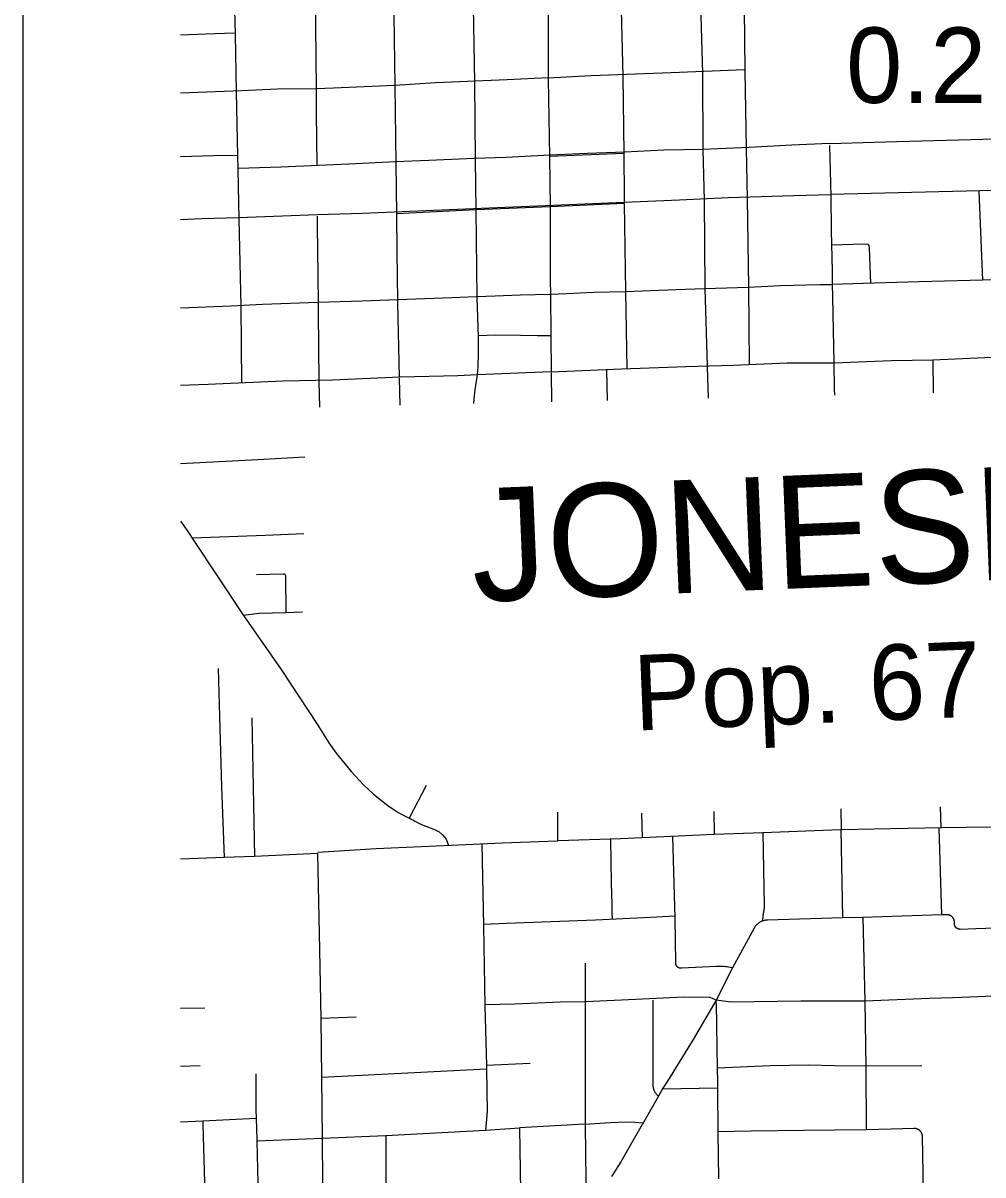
# Model space of a CAD drawing. Extents: x 309348 to 309445, y 336383 to 336484.
# Drawn here: x 309347.661 to 309348.736, y 336398.714 to 336400.005 of the extents above; entities that cross this region are included whole.
import ezdxf

# ---------------------------------------------------------------- set-up
doc = ezdxf.new("R2010")
doc.units = 0
doc.layers.add('R_Annotation', color=7, linetype='Continuous')
doc.layers.add('R_Border Notes', color=7, linetype='Continuous')

msp = doc.modelspace()

# ---------------------------------------------------------------- linework, layer by layer
at = {"layer": 'R_Annotation'}
msp.add_line((309348.736, 336399.7168), (309348.7321, 336399.8167), dxfattribs=at)
for points in [[(309348.4191, 336400.053), (309348.4191, 336400.0524), (309348.4222, 336399.9485)], [(309348.0759, 336400.0402), (309348.0772, 336399.9351)], [(309348.1648, 336400.0446), (309348.1667, 336399.9388)], [(309348.2491, 336400.0465), (309348.2492, 336399.9422)], [(309348.3301, 336400.0497), (309348.3327, 336399.9455)], [(309347.8972, 336400.0337), (309347.8982, 336399.9928)], [(309347.9881, 336400.0366), (309347.9893, 336399.9315)], [(309348.4687, 336400.0211), (309348.4696, 336399.9515)], [(309347.8371, 336399.992), (309347.8653, 336399.993), (309347.8972, 336399.9943)], [(309347.8982, 336399.9928), (309347.8996, 336399.9275)], [(309348.2492, 336399.9437), (309348.2972, 336399.9462), (309348.3869, 336399.9498), (309348.4696, 336399.9529)], [(309348.4696, 336399.9515), (309348.4711, 336399.8646)], [(309348.2492, 336399.9437), (309348.2033, 336399.9415), (309348.123, 336399.9382), (309348.0772, 336399.9351)], [(309348.1667, 336399.9388), (309348.1674, 336399.8519)], [(309348.2492, 336399.9422), (309348.2506, 336399.8556)], [(309348.3327, 336399.9455), (309348.3337, 336399.859)], [(309348.4222, 336399.9485), (309348.4224, 336399.8629)], [(309347.9893, 336399.9315), (309347.9454, 336399.931), (309347.9055, 336399.9292), (309347.8468, 336399.9269), (309347.8371, 336399.9265)], [(309347.8996, 336399.9275), (309347.901, 336399.8567)], [(309347.9893, 336399.9315), (309347.9891, 336399.9045), (309347.9899, 336399.8454)], [(309348.0772, 336399.9351), (309348.0086, 336399.9323), (309347.9893, 336399.9315)], [(309348.0772, 336399.9351), (309348.0783, 336399.8477)], [(309348.5645, 336399.87), (309348.6399, 336399.8725), (309348.7228, 336399.8746), (309348.7904, 336399.8766), (309348.8422, 336399.8777), (309348.8945, 336399.8787), (309348.9447, 336399.8795), (309348.9871, 336399.881), (309349.0202, 336399.8814)], [(309348.5645, 336399.87), (309348.5222, 336399.8682), (309348.4743, 336399.8658), (309348.4229, 336399.8635), (309348.3786, 336399.8625), (309348.3351, 336399.8602), (309348.2929, 336399.8589), (309348.2514, 336399.8571), (309348.2017, 336399.8545), (309348.1662, 336399.8532), (309348.1153, 336399.8512), (309348.0782, 336399.8494), (309348.0257, 336399.8471), (309347.9495, 336399.8435), (309347.9016, 336399.8422)], [(309348.3337, 336399.859), (309348.2506, 336399.8556)], [(309348.3337, 336399.859), (309348.3337, 336399.8578), (309348.3343, 336399.8114), (309348.3344, 336399.8028)], [(309348.4224, 336399.8629), (309348.4238, 336399.8065)], [(309348.4711, 336399.8646), (309348.4721, 336399.8085)], [(309348.5645, 336399.8679), (309348.5657, 336399.8111)], [(309347.901, 336399.8567), (309347.8738, 336399.8563), (309347.8371, 336399.8551)], [(309347.901, 336399.8567), (309347.9013, 336399.8409)], [(309348.0783, 336399.8477), (309348.079, 336399.7914)], [(309348.1674, 336399.8519), (309348.168, 336399.7958)], [(309348.2506, 336399.8556), (309348.2512, 336399.7991)], [(309347.9013, 336399.8409), (309347.9025, 336399.7854)], [(309347.9024, 336399.7871), (309347.9901, 336399.7904), (309348.0409, 336399.7922), (309348.1294, 336399.7958), (309348.2993, 336399.8028), (309348.3961, 336399.8071), (309348.4507, 336399.8095), (309348.5245, 336399.8118), (309348.5656, 336399.8128)], [(309348.4721, 336399.8085), (309348.4734, 336399.709)], [(309348.7934, 336399.8187), (309348.5656, 336399.8128)], [(309348.5657, 336399.8111), (309348.5663, 336399.7725), (309348.5673, 336399.7269), (309348.5675, 336399.7119)], [(309348.168, 336399.7958), (309348.079, 336399.7914)], [(309348.2512, 336399.7991), (309348.168, 336399.7958)], [(309348.168, 336399.7958), (309348.169, 336399.6973)], [(309348.3344, 336399.8028), (309348.2512, 336399.7991)], [(309348.2512, 336399.7991), (309348.2512, 336399.7562), (309348.2513, 336399.7182), (309348.2516, 336399.7001)], [(309348.3344, 336399.8028), (309348.3356, 336399.7043)], [(309348.4238, 336399.8065), (309348.4248, 336399.7076)], [(309347.8371, 336399.7849), (309347.8612, 336399.786), (309347.9024, 336399.7871)], [(309347.9025, 336399.7854), (309347.9047, 336399.6876)], [(309347.9901, 336399.7885), (309347.9904, 336399.7781), (309347.991, 336399.7224), (309347.9912, 336399.6905)], [(309348.079, 336399.7914), (309348.0794, 336399.7491), (309348.0803, 336399.6939)], [(309348.5666, 336399.7566), (309348.603, 336399.7575), (309348.6074, 336399.7571), (309348.6083, 336399.7559), (309348.6089, 336399.7531), (309348.6091, 336399.7429), (309348.6102, 336399.7133)], [(309348.7942, 336399.7185), (309348.736, 336399.7168)], [(309348.1689, 336399.6985), (309348.1897, 336399.6994), (309348.2179, 336399.7003), (309348.2516, 336399.7013), (309348.2698, 336399.7018), (309348.3004, 336399.7033), (309348.3356, 336399.7043)], [(309348.3356, 336399.7043), (309348.3924, 336399.7065), (309348.4243, 336399.7075), (309348.4734, 336399.709)], [(309348.3356, 336399.7043), (309348.3371, 336399.6179)], [(309348.4248, 336399.7076), (309348.4274, 336399.6208)], [(309348.4734, 336399.709), (309348.5095, 336399.7108), (309348.5533, 336399.7121), (309348.5675, 336399.7119)], [(309348.4734, 336399.709), (309348.4743, 336399.6225)], [(309348.665, 336399.7149), (309348.6019, 336399.7131), (309348.5675, 336399.7119)], [(309348.5675, 336399.7119), (309348.5677, 336399.6984), (309348.5685, 336399.6605), (309348.5691, 336399.6243)], [(309348.736, 336399.7168), (309348.665, 336399.7149)], [(309347.8371, 336399.6858), (309347.894, 336399.6883), (309347.9291, 336399.69), (309347.9911, 336399.6921)], [(309347.9911, 336399.6921), (309348.0406, 336399.6939), (309348.0707, 336399.6947), (309348.1412, 336399.6974), (309348.1689, 336399.6985)], [(309348.0803, 336399.6939), (309348.0804, 336399.692), (309348.0821, 336399.6081)], [(309348.169, 336399.6973), (309348.1707, 336399.6535)], [(309348.2516, 336399.7001), (309348.2522, 336399.6553)], [(309347.9047, 336399.6876), (309347.9053, 336399.6016)], [(309347.9912, 336399.6905), (309347.9912, 336399.6893), (309347.9915, 336399.6807), (309347.992, 336399.6034)], [(309348.1707, 336399.6535), (309348.1708, 336399.6446), (309348.1708, 336399.6347), (309348.1703, 336399.6199), (309348.1697, 336399.6108)], [(309348.1707, 336399.6548), (309348.1905, 336399.6555), (309348.2181, 336399.6553), (309348.2366, 336399.6549), (309348.2522, 336399.6549)], [(309348.2522, 336399.6553), (309348.2525, 336399.6142)], [(309348.5691, 336399.6243), (309348.6338, 336399.627), (309348.6801, 336399.6275), (309348.7383, 336399.6301), (309348.793, 336399.6313)], [(309348.6801, 336399.6275), (309348.6806, 336399.5905)], [(309348.2525, 336399.6142), (309348.1697, 336399.6108)], [(309348.2525, 336399.6142), (309348.3316, 336399.6177), (309348.4034, 336399.62), (309348.4564, 336399.6218), (309348.517, 336399.6241), (309348.5691, 336399.6243)], [(309348.3143, 336399.6169), (309348.3151, 336399.5821)], [(309348.4274, 336399.6196), (309348.4274, 336399.6193), (309348.4283, 336399.5847)], [(309348.5691, 336399.6243), (309348.5696, 336399.5951), (309348.5698, 336399.5879)], [(309348.1697, 336399.6108), (309348.1479, 336399.6098), (309348.0834, 336399.6082), (309348.0073, 336399.605), (309347.9519, 336399.6038), (309347.868, 336399.5999), (309347.8371, 336399.5989)], [(309347.992, 336399.6034), (309347.9927, 336399.5747)], [(309348.0822, 336399.6069), (309348.083, 336399.5768)], [(309348.1696, 336399.6101), (309348.168, 336399.6015), (309348.1668, 336399.5941), (309348.1657, 336399.5844), (309348.1654, 336399.5787)], [(309348.2526, 336399.613), (309348.253, 336399.5807)], [(309347.9766, 336399.5184), (309347.9239, 336399.5154), (309347.8371, 336399.5111)], [(309347.8371, 336399.4469), (309347.8453, 336399.4352), (309347.851, 336399.4267)], [(309347.8501, 336399.4281), (309347.9321, 336399.4311), (309347.9753, 336399.4329)], [(309347.851, 336399.4267), (309347.9077, 336399.3411)], [(309347.9222, 336399.3872), (309347.9522, 336399.3876), (309347.9525, 336399.3877), (309347.9528, 336399.3877), (309347.9531, 336399.3877), (309347.9534, 336399.3876), (309347.9537, 336399.3875), (309347.954, 336399.3873), (309347.9542, 336399.3871), (309347.9544, 336399.3868), (309347.9545, 336399.3865), (309347.9546, 336399.3862), (309347.9547, 336399.3859), (309347.9547, 336399.3859), (309347.9553, 336399.3446)], [(309347.9074, 336399.3416), (309347.9254, 336399.3438), (309347.9553, 336399.3446), (309347.974, 336399.3452)], [(309347.9077, 336399.3411), (309347.9498, 336399.2804), (309347.9903, 336399.2191), (309348.0033, 336399.1985), (309348.0116, 336399.1868), (309348.0283, 336399.1662), (309348.0422, 336399.1513), (309348.0532, 336399.1408), (309348.0695, 336399.128), (309348.0809, 336399.1202), (309348.0903, 336399.1154), (309348.1072, 336399.1067), (309348.1219, 336399.1012), (309348.1269, 336399.0987), (309348.1306, 336399.0953), (309348.1347, 336399.0905), (309348.1375, 336399.0831)], [(309347.8794, 336399.2818), (309347.8809, 336399.2278)], [(309347.8809, 336399.2278), (309347.883, 336399.1491)], [(309347.917, 336399.2264), (309347.9202, 336399.0711)], [(309347.883, 336399.1491), (309347.8861, 336399.07)], [(309348.1124, 336399.1505), (309348.0933, 336399.1139)], [(309348.5769, 336399.1242), (309348.5773, 336399.101)], [(309348.6884, 336399.1266), (309348.6891, 336399.1029)], [(309348.2594, 336399.1208), (309348.2596, 336399.0883)], [(309348.3535, 336399.1194), (309348.3543, 336399.0919)], [(309348.4346, 336399.1212), (309348.4351, 336399.0956)], [(309348.4898, 336399.0973), (309348.4351, 336399.0956)], [(309348.4898, 336399.0973), (309348.4911, 336399.0159), (309348.4911, 336399.0148), (309348.4911, 336399.0137), (309348.491, 336399.0126), (309348.4909, 336399.0115), (309348.4907, 336399.0104), (309348.4905, 336399.0093), (309348.4903, 336399.0082), (309348.4901, 336399.0071), (309348.4899, 336399.0059), (309348.4897, 336399.0047), (309348.4896, 336399.0035), (309348.4895, 336399.0023), (309348.4894, 336399.0011), (309348.4894, 336398.9999), (309348.4894, 336398.9987)], [(309348.5771, 336399.101), (309348.5768, 336399.101), (309348.4898, 336399.0973)], [(309348.6898, 336399.1029), (309348.5768, 336399.101)], [(309348.5771, 336399.101), (309348.5788, 336399.0022)], [(309348.687, 336399.1028), (309348.69, 336399.0055)], [(309348.8015, 336399.1046), (309348.6898, 336399.1029)], [(309348.2596, 336399.0883), (309348.1976, 336399.0857), (309348.1404, 336399.0832), (309348.0562, 336399.0795), (309347.991, 336399.0756)], [(309348.1748, 336399.0847), (309348.1767, 336398.9934)], [(309348.4351, 336399.0956), (309348.3301, 336399.0909), (309348.2604, 336399.0884)], [(309348.319, 336399.0905), (309348.3196, 336399.0411), (309348.3203, 336399.0175), (309348.3205, 336399.0098), (309348.3208, 336399.0005)], [(309348.3883, 336399.0935), (309348.3909, 336399.002)], [(309347.9906, 336399.0744), (309347.9202, 336399.0711)], [(309347.9906, 336399.0744), (309347.9928, 336398.9664)], [(309347.8861, 336399.07), (309347.8371, 336399.0679)], [(309347.9202, 336399.0711), (309347.8861, 336399.07)], [(309348.3909, 336399.004), (309348.3638, 336399.0024), (309348.3022, 336398.9997), (309348.2024, 336398.9958), (309348.1767, 336398.9946)], [(309348.3909, 336399.002), (309348.3916, 336398.9521), (309348.3916, 336398.9519), (309348.3916, 336398.9517), (309348.3917, 336398.9515), (309348.3917, 336398.9512), (309348.3917, 336398.951), (309348.3917, 336398.9508), (309348.3918, 336398.9506), (309348.3918, 336398.9504), (309348.3919, 336398.9502), (309348.392, 336398.95), (309348.392, 336398.9498), (309348.3921, 336398.9496), (309348.3922, 336398.9494), (309348.3923, 336398.9492), (309348.3924, 336398.949), (309348.3925, 336398.9488), (309348.3926, 336398.9486), (309348.3927, 336398.9484), (309348.3929, 336398.9483), (309348.393, 336398.9481), (309348.3931, 336398.9479), (309348.3933, 336398.9478), (309348.3934, 336398.9476), (309348.3936, 336398.9474), (309348.3937, 336398.9473), (309348.3939, 336398.9472), (309348.3941, 336398.947)], [(309348.4894, 336398.9987), (309348.4889, 336398.9985), (309348.4883, 336398.9983), (309348.4878, 336398.998), (309348.4873, 336398.9978), (309348.4868, 336398.9975), (309348.4863, 336398.9972), (309348.4858, 336398.9969), (309348.4853, 336398.9966), (309348.4848, 336398.9963), (309348.4844, 336398.996), (309348.4839, 336398.9956), (309348.4835, 336398.9952), (309348.4831, 336398.9948), (309348.4827, 336398.9944), (309348.4823, 336398.994), (309348.4819, 336398.9936), (309348.4815, 336398.9931), (309348.4812, 336398.9927), (309348.4808, 336398.9922), (309348.4805, 336398.9917), (309348.4802, 336398.9912), (309348.4799, 336398.9907), (309348.4555, 336398.9461)], [(309348.5788, 336399.0022), (309348.4949, 336398.9995), (309348.4943, 336398.9995), (309348.4938, 336398.9995), (309348.4932, 336398.9995), (309348.4927, 336398.9994), (309348.4921, 336398.9993), (309348.4916, 336398.9992), (309348.491, 336398.9991), (309348.4905, 336398.999), (309348.49, 336398.9988), (309348.4894, 336398.9987)], [(309348.6016, 336399.0027), (309348.5788, 336399.0022)], [(309348.69, 336399.0055), (309348.6016, 336399.0027)], [(309348.6016, 336399.0027), (309348.6038, 336398.9087)], [(309348.6962, 336399.0057), (309348.6959, 336399.0057), (309348.6956, 336399.0057), (309348.6923, 336399.0056), (309348.69, 336399.0055)], [(309348.7836, 336398.9917), (309348.7282, 336398.9899), (309348.7109, 336398.9893), (309348.7106, 336398.9893), (309348.7104, 336398.9893), (309348.7102, 336398.9894), (309348.71, 336398.9894), (309348.7098, 336398.9894), (309348.7095, 336398.9894), (309348.7093, 336398.9895), (309348.7091, 336398.9895), (309348.7089, 336398.9896), (309348.7087, 336398.9897), (309348.7085, 336398.9897), (309348.7083, 336398.9898), (309348.7081, 336398.9899), (309348.7079, 336398.99), (309348.7077, 336398.9901), (309348.7075, 336398.9902), (309348.7073, 336398.9903), (309348.7071, 336398.9904), (309348.7069, 336398.9906), (309348.7067, 336398.9907), (309348.7066, 336398.9908), (309348.7064, 336398.991), (309348.7062, 336398.9911), (309348.7061, 336398.9913), (309348.7059, 336398.9915), (309348.7058, 336398.9916), (309348.7056, 336398.9918), (309348.7055, 336398.992), (309348.7054, 336398.9922), (309348.7053, 336398.9924), (309348.7051, 336398.9925), (309348.705, 336398.9927), (309348.7049, 336398.9929), (309348.7048, 336398.9931), (309348.7048, 336398.9933), (309348.7047, 336398.9935), (309348.7046, 336398.9938), (309348.7045, 336398.994), (309348.7045, 336398.9942), (309348.7044, 336398.9944), (309348.7044, 336398.9946), (309348.7044, 336398.9948), (309348.7043, 336398.9951), (309348.7043, 336398.9953), (309348.7043, 336398.9955), (309348.7043, 336398.9957), (309348.7043, 336398.9959), (309348.7043, 336398.9962), (309348.7043, 336398.9964), (309348.7043, 336398.9967), (309348.7044, 336398.997), (309348.7044, 336398.9973), (309348.7043, 336398.9976), (309348.7043, 336398.9979), (309348.7043, 336398.9982), (309348.7043, 336398.9984), (309348.7042, 336398.9987), (309348.7042, 336398.999), (309348.7041, 336398.9993), (309348.704, 336398.9996), (309348.7039, 336398.9999), (309348.7038, 336399.0002), (309348.7037, 336399.0004), (309348.7036, 336399.0007), (309348.7035, 336399.001), (309348.7034, 336399.0012), (309348.7032, 336399.0015), (309348.7031, 336399.0017), (309348.7029, 336399.002), (309348.7027, 336399.0022), (309348.7025, 336399.0025), (309348.7024, 336399.0027), (309348.7022, 336399.0029), (309348.702, 336399.0031), (309348.7018, 336399.0033), (309348.7015, 336399.0035), (309348.7013, 336399.0037), (309348.7011, 336399.0039), (309348.7009, 336399.0041), (309348.7006, 336399.0043), (309348.7004, 336399.0044), (309348.7001, 336399.0046), (309348.6999, 336399.0047), (309348.6996, 336399.0049), (309348.6993, 336399.005), (309348.6991, 336399.0051), (309348.6988, 336399.0052), (309348.6985, 336399.0053), (309348.6982, 336399.0054), (309348.698, 336399.0055), (309348.6977, 336399.0055), (309348.6974, 336399.0056), (309348.6971, 336399.0056), (309348.6968, 336399.0057), (309348.6965, 336399.0057), (309348.6962, 336399.0057)], [(309348.1767, 336398.9934), (309348.1782, 336398.9034)], [(309347.9928, 336398.9664), (309347.9944, 336398.8894)], [(309348.2907, 336398.9514), (309348.2906, 336398.9066)], [(309348.4555, 336398.9461), (309348.451, 336398.9469), (309348.4495, 336398.9472), (309348.448, 336398.9474), (309348.4464, 336398.9476), (309348.4449, 336398.9477), (309348.4434, 336398.9477), (309348.4418, 336398.9477), (309348.4403, 336398.9476), (309348.4368, 336398.9475), (309348.399, 336398.9458), (309348.3988, 336398.9457), (309348.3986, 336398.9457), (309348.3983, 336398.9457), (309348.3981, 336398.9457), (309348.3979, 336398.9457), (309348.3977, 336398.9457), (309348.3975, 336398.9457), (309348.3972, 336398.9457), (309348.397, 336398.9458), (309348.3968, 336398.9458), (309348.3966, 336398.9458), (309348.3964, 336398.9459), (309348.3962, 336398.9459), (309348.396, 336398.946), (309348.3958, 336398.9461), (309348.3956, 336398.9462), (309348.3954, 336398.9462), (309348.3952, 336398.9463), (309348.395, 336398.9464), (309348.3948, 336398.9465), (309348.3946, 336398.9466), (309348.3944, 336398.9468), (309348.3942, 336398.9469), (309348.3941, 336398.947)], [(309348.4555, 336398.9461), (309348.4373, 336398.91)], [(309348.8044, 336398.9167), (309348.7026, 336398.9127)], [(309348.4373, 336398.91), (309348.4308, 336398.9128), (309348.4011, 336398.9132), (309348.3311, 336398.91), (309348.2908, 336398.9082), (309348.2629, 336398.9077), (309348.2118, 336398.9055), (309348.1781, 336398.9048)], [(309348.2906, 336398.9066), (309348.2906, 336398.8745), (309348.2905, 336398.7694)], [(309348.3663, 336398.9099), (309348.3663, 336398.8727), (309348.3663, 336398.8336), (309348.3662, 336398.8161), (309348.3662, 336398.8155), (309348.3662, 336398.8149), (309348.3663, 336398.8143), (309348.3664, 336398.8137), (309348.3664, 336398.8131), (309348.3666, 336398.8125), (309348.3667, 336398.8119), (309348.3668, 336398.8114), (309348.367, 336398.8108), (309348.3672, 336398.8102), (309348.3674, 336398.8096), (309348.3676, 336398.8091), (309348.3679, 336398.8085), (309348.3682, 336398.808), (309348.3684, 336398.8074), (309348.3687, 336398.8069), (309348.3691, 336398.8064), (309348.3694, 336398.8059), (309348.3698, 336398.8054), (309348.3701, 336398.805), (309348.3705, 336398.8045), (309348.3709, 336398.804), (309348.3713, 336398.8036), (309348.3718, 336398.8032), (309348.3722, 336398.8028), (309348.3727, 336398.8024)], [(309348.4373, 336398.91), (309348.4114, 336398.8659), (309348.3827, 336398.8193), (309348.3776, 336398.8111), (309348.3755, 336398.8073)], [(309348.4374, 336398.9061), (309348.4373, 336398.91)], [(309348.6038, 336398.9087), (309348.5322, 336398.9087), (309348.4537, 336398.9077), (309348.4373, 336398.91)], [(309348.4374, 336398.9061), (309348.4384, 336398.8328)], [(309348.6759, 336398.9116), (309348.6038, 336398.9087)], [(309348.6038, 336398.9087), (309348.6049, 336398.8345)], [(309348.7026, 336398.9127), (309348.6759, 336398.9116)], [(309347.8371, 336398.901), (309347.8645, 336398.9013)], [(309348.0338, 336398.8909), (309347.9944, 336398.8894)], [(309348.1782, 336398.9034), (309348.1799, 336398.8366)], [(309347.9944, 336398.8894), (309347.9951, 336398.8231)], [(309348.2289, 336398.8389), (309348.1799, 336398.8366)], [(309347.8592, 336398.8364), (309347.8371, 336398.8354)], [(309347.9215, 336398.8275), (309347.9217, 336398.787), (309347.922, 336398.7773)], [(309348.0622, 336398.8265), (309347.9951, 336398.8231)], [(309348.18, 336398.8325), (309348.0622, 336398.8265)], [(309348.18, 336398.8325), (309348.1808, 336398.7851), (309348.1788, 336398.7639)], [(309348.1799, 336398.8366), (309348.18, 336398.8325)], [(309348.6049, 336398.8358), (309348.5706, 336398.8362), (309348.5403, 336398.8372), (309348.4984, 336398.8362), (309348.4384, 336398.8338)], [(309348.4384, 336398.8328), (309348.4387, 336398.8184), (309348.4388, 336398.8104)], [(309348.6678, 336398.8362), (309348.6049, 336398.8358)], [(309348.6049, 336398.8345), (309348.6056, 336398.7646)], [(309347.9951, 336398.8231), (309347.9957, 336398.7549)], [(309348.3727, 336398.8024), (309348.3547, 336398.7709), (309348.3545, 336398.7705)], [(309348.3755, 336398.8073), (309348.3728, 336398.8026), (309348.3727, 336398.8024)], [(309348.4386, 336398.8113), (309348.3777, 336398.8102)], [(309348.4388, 336398.8104), (309348.4393, 336398.7612)], [(309347.922, 336398.7773), (309347.8623, 336398.7743), (309347.8622, 336398.7743)], [(309347.922, 336398.7773), (309347.9227, 336398.7542), (309347.9228, 336398.7517)], [(309347.8622, 336398.7743), (309347.8371, 336398.7731)], [(309347.8622, 336398.7743), (309347.8623, 336398.7707), (309347.8644, 336398.6926), (309347.8641, 336398.6478)], [(309348.1788, 336398.7639), (309348.0671, 336398.7579)], [(309348.2168, 336398.7665), (309348.1788, 336398.7639)], [(309348.2901, 336398.7708), (309348.2168, 336398.7668), (309348.2168, 336398.7665)], [(309348.2168, 336398.7665), (309348.2197, 336398.602)], [(309348.2901, 336398.7708), (309348.3187, 336398.7727), (309348.336, 336398.7735), (309348.3469, 336398.773), (309348.3547, 336398.7723)], [(309348.2905, 336398.7694), (309348.2916, 336398.6768)], [(309348.3545, 336398.7705), (309348.3305, 336398.7288), (309348.3207, 336398.7134), (309348.3199, 336398.7123)], [(309348.6056, 336398.7646), (309348.5352, 336398.7639), (309348.4767, 336398.7631), (309348.4393, 336398.7625)], [(309348.6658, 336398.7634), (309348.6656, 336398.7636), (309348.6654, 336398.7638), (309348.6651, 336398.764), (309348.6649, 336398.7642), (309348.6647, 336398.7644), (309348.6645, 336398.7645), (309348.6642, 336398.7647), (309348.664, 336398.7648), (309348.6637, 336398.765), (309348.6635, 336398.7651), (309348.6632, 336398.7652), (309348.6629, 336398.7653), (309348.6627, 336398.7655), (309348.6624, 336398.7655), (309348.6621, 336398.7656), (309348.6619, 336398.7657), (309348.6616, 336398.7658), (309348.6613, 336398.7658), (309348.661, 336398.7659), (309348.6607, 336398.7659), (309348.6604, 336398.7659), (309348.6602, 336398.766), (309348.6599, 336398.766), (309348.6596, 336398.766), (309348.6593, 336398.766), (309348.659, 336398.7659), (309348.6587, 336398.7659), (309348.6335, 336398.7654), (309348.6056, 336398.7646)], [(309348.6658, 336398.7634), (309348.666, 336398.7632), (309348.6661, 336398.763), (309348.6663, 336398.7628), (309348.6665, 336398.7625), (309348.6667, 336398.7623), (309348.6668, 336398.7621), (309348.667, 336398.7618), (309348.6671, 336398.7616), (309348.6672, 336398.7613), (309348.6674, 336398.761), (309348.6675, 336398.7608), (309348.6676, 336398.7605), (309348.6677, 336398.7602), (309348.6677, 336398.76), (309348.6678, 336398.7597), (309348.6679, 336398.7594), (309348.6679, 336398.7591), (309348.668, 336398.7588), (309348.668, 336398.7586), (309348.668, 336398.7583), (309348.6681, 336398.758), (309348.6681, 336398.7577), (309348.6681, 336398.7574), (309348.6693, 336398.6944)], [(309347.9957, 336398.7549), (309347.9228, 336398.7517)], [(309347.9228, 336398.7517), (309347.9238, 336398.7049)], [(309348.0671, 336398.7579), (309347.9957, 336398.7549)], [(309347.9957, 336398.7549), (309347.9958, 336398.7499), (309347.9979, 336398.552)], [(309348.0671, 336398.7579), (309348.0675, 336398.6139)], [(309348.4393, 336398.7612), (309348.4399, 336398.7095)]]:
    msp.add_lwpolyline(points, dxfattribs=at)
at = {"layer": 'R_Border Notes'}
msp.add_line((309347.6607, 336395.7269), (309347.6607, 336403.9877), dxfattribs=at)

# ---------------------------------------------------------------- texts
at = {"layer": 'R_Annotation'}
msp.add_text('0.2', height=0.08451, dxfattribs=at).set_placement((309348.583, 336399.9156))
for s, height, p in [('JONESBORO', 0.12664, (309348.1652, 336399.3564)), ('Pop. 67,263', 0.084508, (309348.3464, 336399.212))]:
    msp.add_text(s, height=height, rotation=2.3695, dxfattribs=at).set_placement(p)

doc.saveas('drawing.dxf')
